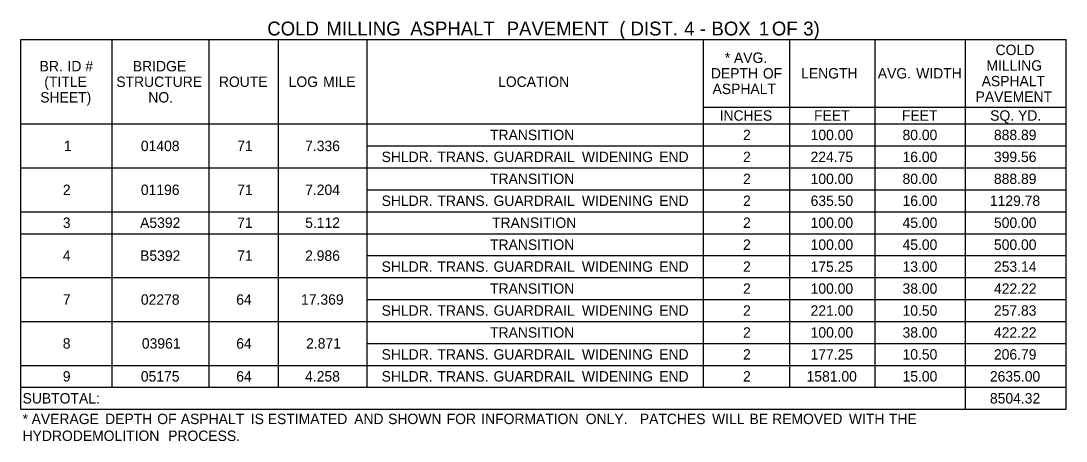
# Model space of a CAD drawing. Extents: x 540541 to 1930787, y -1948574 to 596640.
# Drawn here: x 550379 to 550982, y -1946468 to -1946225 of the extents above; entities that cross this region are included whole.
import ezdxf

# ---------------------------------------------------------------- set-up
doc = ezdxf.new("R2010")
doc.units = 0
doc.layers.add('Default', color=7, linetype='Continuous')

msp = doc.modelspace()

# ---------------------------------------------------------------- linework, layer by layer
at = {"layer": 'Default'}
for p, q in [((550379.2, -1946235.99), (550982.23, -1946235.99)), ((550379.2, -1946235.99), (550982.23, -1946235.99)), ((550379.2, -1946436.84), (550379.2, -1946235.99)), ((550379.2, -1946449.52), (550379.2, -1946235.99)), ((550431.85, -1946436.84), (550431.85, -1946235.99)), ((550487.91, -1946436.84), (550487.91, -1946235.99)), ((550527.88, -1946436.84), (550527.88, -1946235.99)), ((550579.07, -1946436.84), (550579.07, -1946235.99)), ((550773.1, -1946436.84), (550773.1, -1946235.99)), ((550822.82, -1946436.84), (550822.82, -1946235.99)), ((550872.06, -1946436.84), (550872.06, -1946235.99)), ((550924.22, -1946449.52), (550924.22, -1946235.99)), ((550982.23, -1946449.52), (550982.23, -1946235.99)), ((550773.1, -1946274.99), (550872.06, -1946274.99)), ((550773.1, -1946274.99), (550822.82, -1946274.99)), ((550822.82, -1946274.99), (550982.23, -1946274.99)), ((550872.06, -1946386.14), (550872.06, -1946274.99)), ((550379.2, -1946284.74), (550982.23, -1946284.74)), ((550579.07, -1946297.42), (550773.1, -1946297.42)), ((550773.1, -1946297.42), (550982.23, -1946297.42)), ((550773.1, -1946297.42), (550982.23, -1946297.42)), ((550379.2, -1946310.09), (550982.23, -1946310.09)), ((550579.07, -1946310.09), (550982.23, -1946310.09)), ((550579.07, -1946322.77), (550773.1, -1946322.77)), ((550773.1, -1946322.77), (550982.23, -1946322.77)), ((550773.1, -1946322.77), (550982.23, -1946322.77)), ((550379.2, -1946335.44), (550982.23, -1946335.44)), ((550579.07, -1946335.44), (550982.23, -1946335.44)), ((550379.2, -1946348.12), (550982.23, -1946348.12)), ((550579.07, -1946348.12), (550773.1, -1946348.12)), ((550773.1, -1946348.12), (550982.23, -1946348.12)), ((550579.07, -1946360.79), (550773.1, -1946360.79)), ((550773.1, -1946360.79), (550982.23, -1946360.79)), ((550773.1, -1946360.79), (550982.23, -1946360.79)), ((550379.2, -1946373.47), (550982.23, -1946373.47)), ((550579.07, -1946373.47), (550982.23, -1946373.47)), ((550579.07, -1946386.14), (550773.1, -1946386.14)), ((550773.1, -1946386.14), (550982.23, -1946386.14)), ((550773.1, -1946386.14), (550982.23, -1946386.14)), ((550379.2, -1946398.82), (550982.23, -1946398.82)), ((550773.1, -1946398.82), (550982.23, -1946398.82)), ((550579.07, -1946411.49), (550773.1, -1946411.49)), ((550579.07, -1946411.49), (550773.1, -1946411.49)), ((550773.1, -1946411.49), (550982.23, -1946411.49)), ((550773.1, -1946411.49), (550982.23, -1946411.49)), ((550379.2, -1946424.17), (550982.23, -1946424.17)), ((550579.07, -1946424.17), (550872.06, -1946424.17)), ((550579.07, -1946436.84), (550579.07, -1946424.17)), ((550872.06, -1946424.17), (550924.22, -1946424.17)), ((550872.06, -1946436.84), (550872.06, -1946424.17)), ((550924.22, -1946424.17), (550982.23, -1946424.17)), ((550379.2, -1946436.84), (550982.23, -1946436.84)), ((550773.1, -1946436.84), (550982.23, -1946436.84)), ((550379.2, -1946449.52), (550982.23, -1946449.52)), ((550924.22, -1946449.52), (550982.23, -1946449.52))]:
    msp.add_line(p, q, dxfattribs=at)

# ---------------------------------------------------------------- texts
for s, height, p in [('COLD', 8, (550521.36, -1946233.65)), (' MILLING', 8, (550552.48, -1946233.65)), (' ASPHALT', 8, (550600.85, -1946233.65)), (' PAVEMENT', 8, (550656.51, -1946233.65)), (' (', 8, (550721.5, -1946233.65)), (' DIST.', 8, (550727.97, -1946233.65)), (' 4', 8, (550758.87, -1946233.65)), (' -', 8, (550767.93, -1946233.65)), (' BOX', 8, (550774.68, -1946233.65)), (' 1', 8, (550801.99, -1946233.65)), (' OF', 8, (550809.5, -1946233.65)), (' 3)', 8, (550827.61, -1946233.65)), ('COLD', 6, (550941.56, -1946244.99)), ('BR.', 6, (550390, -1946254.37)), (' ID', 6, (550403.86, -1946254.37)), (' #', 6, (550414.15, -1946254.37)), ('BRIDGE', 6, (550443.78, -1946254.37)), ('*', 6, (550785.29, -1946249.49)), (' AVG.', 6, (550788.37, -1946249.49)), ('MILLING', 6, (550936.25, -1946253.99)), ('DEPTH', 6, (550777.28, -1946258.49)), (' OF', 6, (550805.05, -1946258.49)), ('LENGTH', 6, (550829.36, -1946258.49)), ('AVG.', 6, (550873.6, -1946258.49)), (' WIDTH', 6, (550893.52, -1946258.49)), ('(TITLE', 6, (550392.69, -1946263.37)), ('STRUCTURE', 6, (550434.23, -1946263.37)), ('ROUTE', 6, (550493.43, -1946263.37)), ('LOG', 6, (550533.68, -1946263.37)), (' MILE', 6, (550551.34, -1946263.37)), ('LOCATION', 6, (550654.53, -1946263.37)), ('ASPHALT', 6, (550933.52, -1946262.99)), ('SHEET)', 6, (550390.36, -1946272.37)), ('NO.', 6, (550452.71, -1946272.37)), ('ASPHALT', 6, (550778.25, -1946267.49)), ('PAVEMENT', 6, (550930.02, -1946271.99)), ('INCHES', 6, (550782.32, -1946282.87)), ('FEET', 6, (550836.81, -1946282.87)), ('FEET', 6, (550887.51, -1946282.87)), ('SQ.', 6, (550938.43, -1946282.87)), (' YD.', 6, (550952.3, -1946282.87)), ('TRANSITION', 6, (550649.88, -1946294.08)), ('2', 6, (550795.85, -1946294.08)), ('100.00', 6, (550834.83, -1946294.08)), ('80.00', 6, (550887.86, -1946294.08)), ('888.89', 6, (550940.6, -1946294.08)), ('1', 6, (550403.96, -1946300.42)), ('01408', 6, (550448.41, -1946300.42)), ('71', 6, (550504.01, -1946300.42)), ('7.336', 6, (550543.18, -1946300.42)), ('SHLDR.', 6, (550587.32, -1946306.75)), (' TRANS.', 6, (550617.33, -1946306.75)), (' GUARDRAIL', 6, (550649.67, -1946306.75)), (' WIDENING', 6, (550700.62, -1946306.75)), (' END', 6, (550745.27, -1946306.75)), ('2', 6, (550795.85, -1946306.75)), ('224.75', 6, (550834.79, -1946306.75)), ('16.00', 6, (550887.86, -1946306.75)), ('399.56', 6, (550940.6, -1946306.75)), ('TRANSITION', 6, (550649.88, -1946319.43)), ('2', 6, (550795.85, -1946319.43)), ('100.00', 6, (550834.83, -1946319.43)), ('80.00', 6, (550887.86, -1946319.43)), ('888.89', 6, (550940.6, -1946319.43)), ('2', 6, (550403.41, -1946325.77)), ('01196', 6, (550448.42, -1946325.77)), ('71', 6, (550504.01, -1946325.77)), ('7.204', 6, (550543.2, -1946325.77)), ('SHLDR.', 6, (550587.32, -1946332.1)), (' TRANS.', 6, (550617.33, -1946332.1)), (' GUARDRAIL', 6, (550649.67, -1946332.1)), (' WIDENING', 6, (550700.62, -1946332.1)), (' END', 6, (550745.27, -1946332.1)), ('2', 6, (550795.85, -1946332.1)), ('635.50', 6, (550834.83, -1946332.1)), ('16.00', 6, (550887.86, -1946332.1)), ('1129.78', 6, (550938.27, -1946332.1)), ('3', 6, (550403.38, -1946344.78)), ('A5392', 6, (550447.98, -1946344.78)), ('71', 6, (550504.01, -1946344.78)), ('5.112', 6, (550543.21, -1946344.78)), ('TRANSITION', 6, (550651.04, -1946344.78)), ('2', 6, (550795.85, -1946344.78)), ('100.00', 6, (550834.83, -1946344.78)), ('45.00', 6, (550887.86, -1946344.78)), ('500.00', 6, (550940.61, -1946344.78)), ('TRANSITION', 6, (550649.88, -1946357.45)), ('2', 6, (550795.85, -1946357.45)), ('100.00', 6, (550834.83, -1946357.45)), ('45.00', 6, (550887.86, -1946357.45)), ('500.00', 6, (550940.61, -1946357.45)), ('4', 6, (550403.39, -1946363.79)), ('B5392', 6, (550447.98, -1946363.79)), ('71', 6, (550504.01, -1946363.79)), ('2.986', 6, (550543.18, -1946363.79)), ('SHLDR.', 6, (550587.32, -1946370.13)), (' TRANS.', 6, (550617.33, -1946370.13)), (' GUARDRAIL', 6, (550649.67, -1946370.13)), (' WIDENING', 6, (550700.62, -1946370.13)), (' END', 6, (550745.27, -1946370.13)), ('2', 6, (550795.85, -1946370.13)), ('175.25', 6, (550834.79, -1946370.13)), ('13.00', 6, (550887.86, -1946370.13)), ('253.14', 6, (550940.62, -1946370.13)), ('TRANSITION', 6, (550649.88, -1946382.8)), ('2', 6, (550795.85, -1946382.8)), ('100.00', 6, (550834.83, -1946382.8)), ('38.00', 6, (550887.86, -1946382.8)), ('422.22', 6, (550940.63, -1946382.8)), ('7', 6, (550403.38, -1946389.14)), ('02278', 6, (550448.41, -1946389.14)), ('64', 6, (550503.44, -1946389.14)), ('17.369', 6, (550540.85, -1946389.14)), ('SHLDR.', 6, (550587.32, -1946395.48)), (' TRANS.', 6, (550617.33, -1946395.48)), (' GUARDRAIL', 6, (550649.67, -1946395.48)), (' WIDENING', 6, (550700.62, -1946395.48)), (' END', 6, (550745.27, -1946395.48)), ('2', 6, (550795.85, -1946395.48)), ('221.00', 6, (550834.83, -1946395.48)), ('10.50', 6, (550887.86, -1946395.48)), ('257.83', 6, (550940.6, -1946395.48)), ('TRANSITION', 6, (550649.88, -1946408.15)), ('2', 6, (550795.85, -1946408.15)), ('100.00', 6, (550834.83, -1946408.15)), ('38.00', 6, (550887.86, -1946408.15)), ('422.22', 6, (550940.63, -1946408.15)), ('8', 6, (550403.38, -1946414.49)), ('03961', 6, (550449, -1946414.49)), ('64', 6, (550503.44, -1946414.49)), ('2.871', 6, (550543.76, -1946414.49)), ('SHLDR.', 6, (550587.32, -1946420.83)), (' TRANS.', 6, (550617.33, -1946420.83)), (' GUARDRAIL', 6, (550649.67, -1946420.83)), (' WIDENING', 6, (550700.62, -1946420.83)), (' END', 6, (550745.27, -1946420.83)), ('2', 6, (550795.85, -1946420.83)), ('177.25', 6, (550834.79, -1946420.83)), ('10.50', 6, (550887.86, -1946420.83)), ('206.79', 6, (550940.6, -1946420.83)), ('9', 6, (550403.38, -1946433.5)), ('05175', 6, (550448.39, -1946433.5)), ('64', 6, (550503.44, -1946433.5)), ('4.258', 6, (550543.18, -1946433.5)), ('SHLDR.', 6, (550587.32, -1946433.5)), (' TRANS.', 6, (550617.33, -1946433.5)), (' GUARDRAIL', 6, (550649.67, -1946433.5)), (' WIDENING', 6, (550700.62, -1946433.5)), (' END', 6, (550745.27, -1946433.5)), ('2', 6, (550795.85, -1946433.5)), ('1581.00', 6, (550832.5, -1946433.5)), ('15.00', 6, (550887.86, -1946433.5)), ('2635.00', 6, (550938.28, -1946433.5)), ('SUBTOTAL:', 6, (550380.17, -1946446.18)), ('8504.32', 6, (550938.29, -1946446.18)), ('*', 6, (550380.17, -1946458.07)), (' AVERAGE', 6, (550383.14, -1946458.07)), (' DEPTH', 6, (550425.56, -1946458.07)), (' OF', 6, (550455.63, -1946458.07)), (' ASPHALT', 6, (550469.21, -1946458.07)), (' IS', 6, (550509.58, -1946458.07)), (' ESTIMATED', 6, (550519.39, -1946458.07)), (' AND', 6, (550569.25, -1946458.07)), (' SHOWN', 6, (550588.84, -1946458.07)), (' FOR', 6, (550622.61, -1946458.07)), (' INFORMATION', 6, (550642.52, -1946458.07)), (' ONLY.', 6, (550702.85, -1946458.07)), ('   PATCHES', 6, (550729.6, -1946458.07)), (' WILL', 6, (550775.75, -1946458.07)), (' BE', 6, (550797.34, -1946458.07)), (' REMOVED', 6, (550810.41, -1946458.07)), (' WITH', 6, (550854.68, -1946458.07)), (' THE', 6, (550877.75, -1946458.07)), ('HYDRODEMOLITION', 6, (550380.17, -1946467.82)), (' PROCESS.', 6, (550461.93, -1946467.82))]:
    msp.add_text(s, height=height, dxfattribs=at).set_placement(p)

doc.saveas('drawing.dxf')
